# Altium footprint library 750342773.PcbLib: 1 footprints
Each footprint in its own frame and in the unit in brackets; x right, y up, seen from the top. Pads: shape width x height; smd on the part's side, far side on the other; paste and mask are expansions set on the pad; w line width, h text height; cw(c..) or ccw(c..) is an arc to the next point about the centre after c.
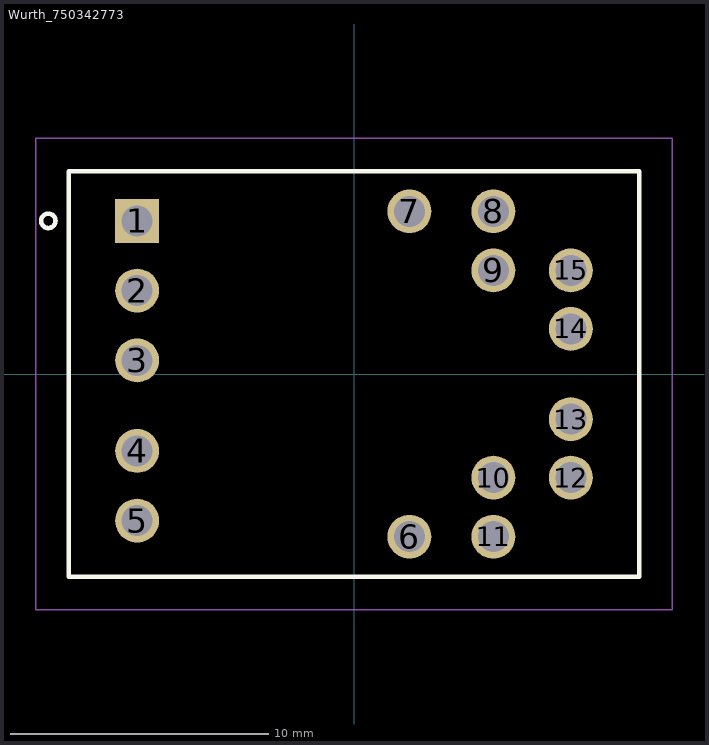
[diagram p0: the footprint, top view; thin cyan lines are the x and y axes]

## Wurth_750342773 [mm] "TRANSFORMER, 80 uH, 10%, THRU"
height 23.3
pads (15):
  rect 1.7x1.7 / inner round 1.7 / far side rect 1.7x1.7 hole 1.2 paste+0: 1(-8.395,5.93)
  round 1.7 hole 1.2 paste+0: 2(-8.395,3.23) 3(-8.395,0.53) 4(-8.395,-2.98) 5(-8.395,-5.68) 6(2.145,-6.3) 12(8.395,-4.01) 13(8.395,-1.75) 14(8.395,1.75) 15(8.395,4.01)
  round 1.7 hole 1.2: 7(2.145,6.3) 8(5.395,6.3) 9(5.395,4.01) 10(5.395,-4.01) 11(5.395,-6.3)
Top Overlay:
  circle w0.178: c-11.836,5.93 r0.279
  lines w0.178: -11.05,-7.85 -11.05,7.85 11.05,7.85 11.05,-7.85 -11.05,-7.85
  text ".Designator" at -1.524,9.271 h1.02
Bottom Overlay:
  lines w0.178: -11.05,-7.85 -11.05,-3.556 ; -11.05,-1.905 -11.05,2.159 ; -11.05,3.81 -11.05,7.85 ; -10.541,-7.85 -6.477,-7.85 ; -10.287,7.85 -6.223,7.85 ; -4.953,-7.85 -0.889,-7.85 ; -4.699,7.85 -0.635,7.85 ; 0.762,-7.85 4.826,-7.85 ; 1.016,7.85 5.08,7.85 ; 6.477,-7.85 10.541,-7.85 ; 6.731,7.85 10.795,7.85 ; 11.05,-7.85 11.05,-3.429 ; 11.05,-1.905 11.05,2.159 ; 11.05,3.81 11.05,7.85
Mechanical 5:
  lines w0.127: -11.05,-7.85 -11.05,7.85 11.05,7.85 11.05,-7.85 -11.05,-7.85
  text ".Designator" at -1.524,-0.508 h1.02
Mechanical 15:
  lines w0.05: -12.32,-9.12 12.32,-9.12 12.32,9.12 -12.32,9.12 -12.32,-9.12
Mechanical 17:
  text "LEAD LENGTH IS 3.2 MM" at -11.659,-9.696 h1.14
3D body: height 23.3, standoff 0, extent -11.05,-7.85 11.05,7.85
